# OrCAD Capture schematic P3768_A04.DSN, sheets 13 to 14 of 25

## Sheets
13 0012_BUTTON MCU: size Custom
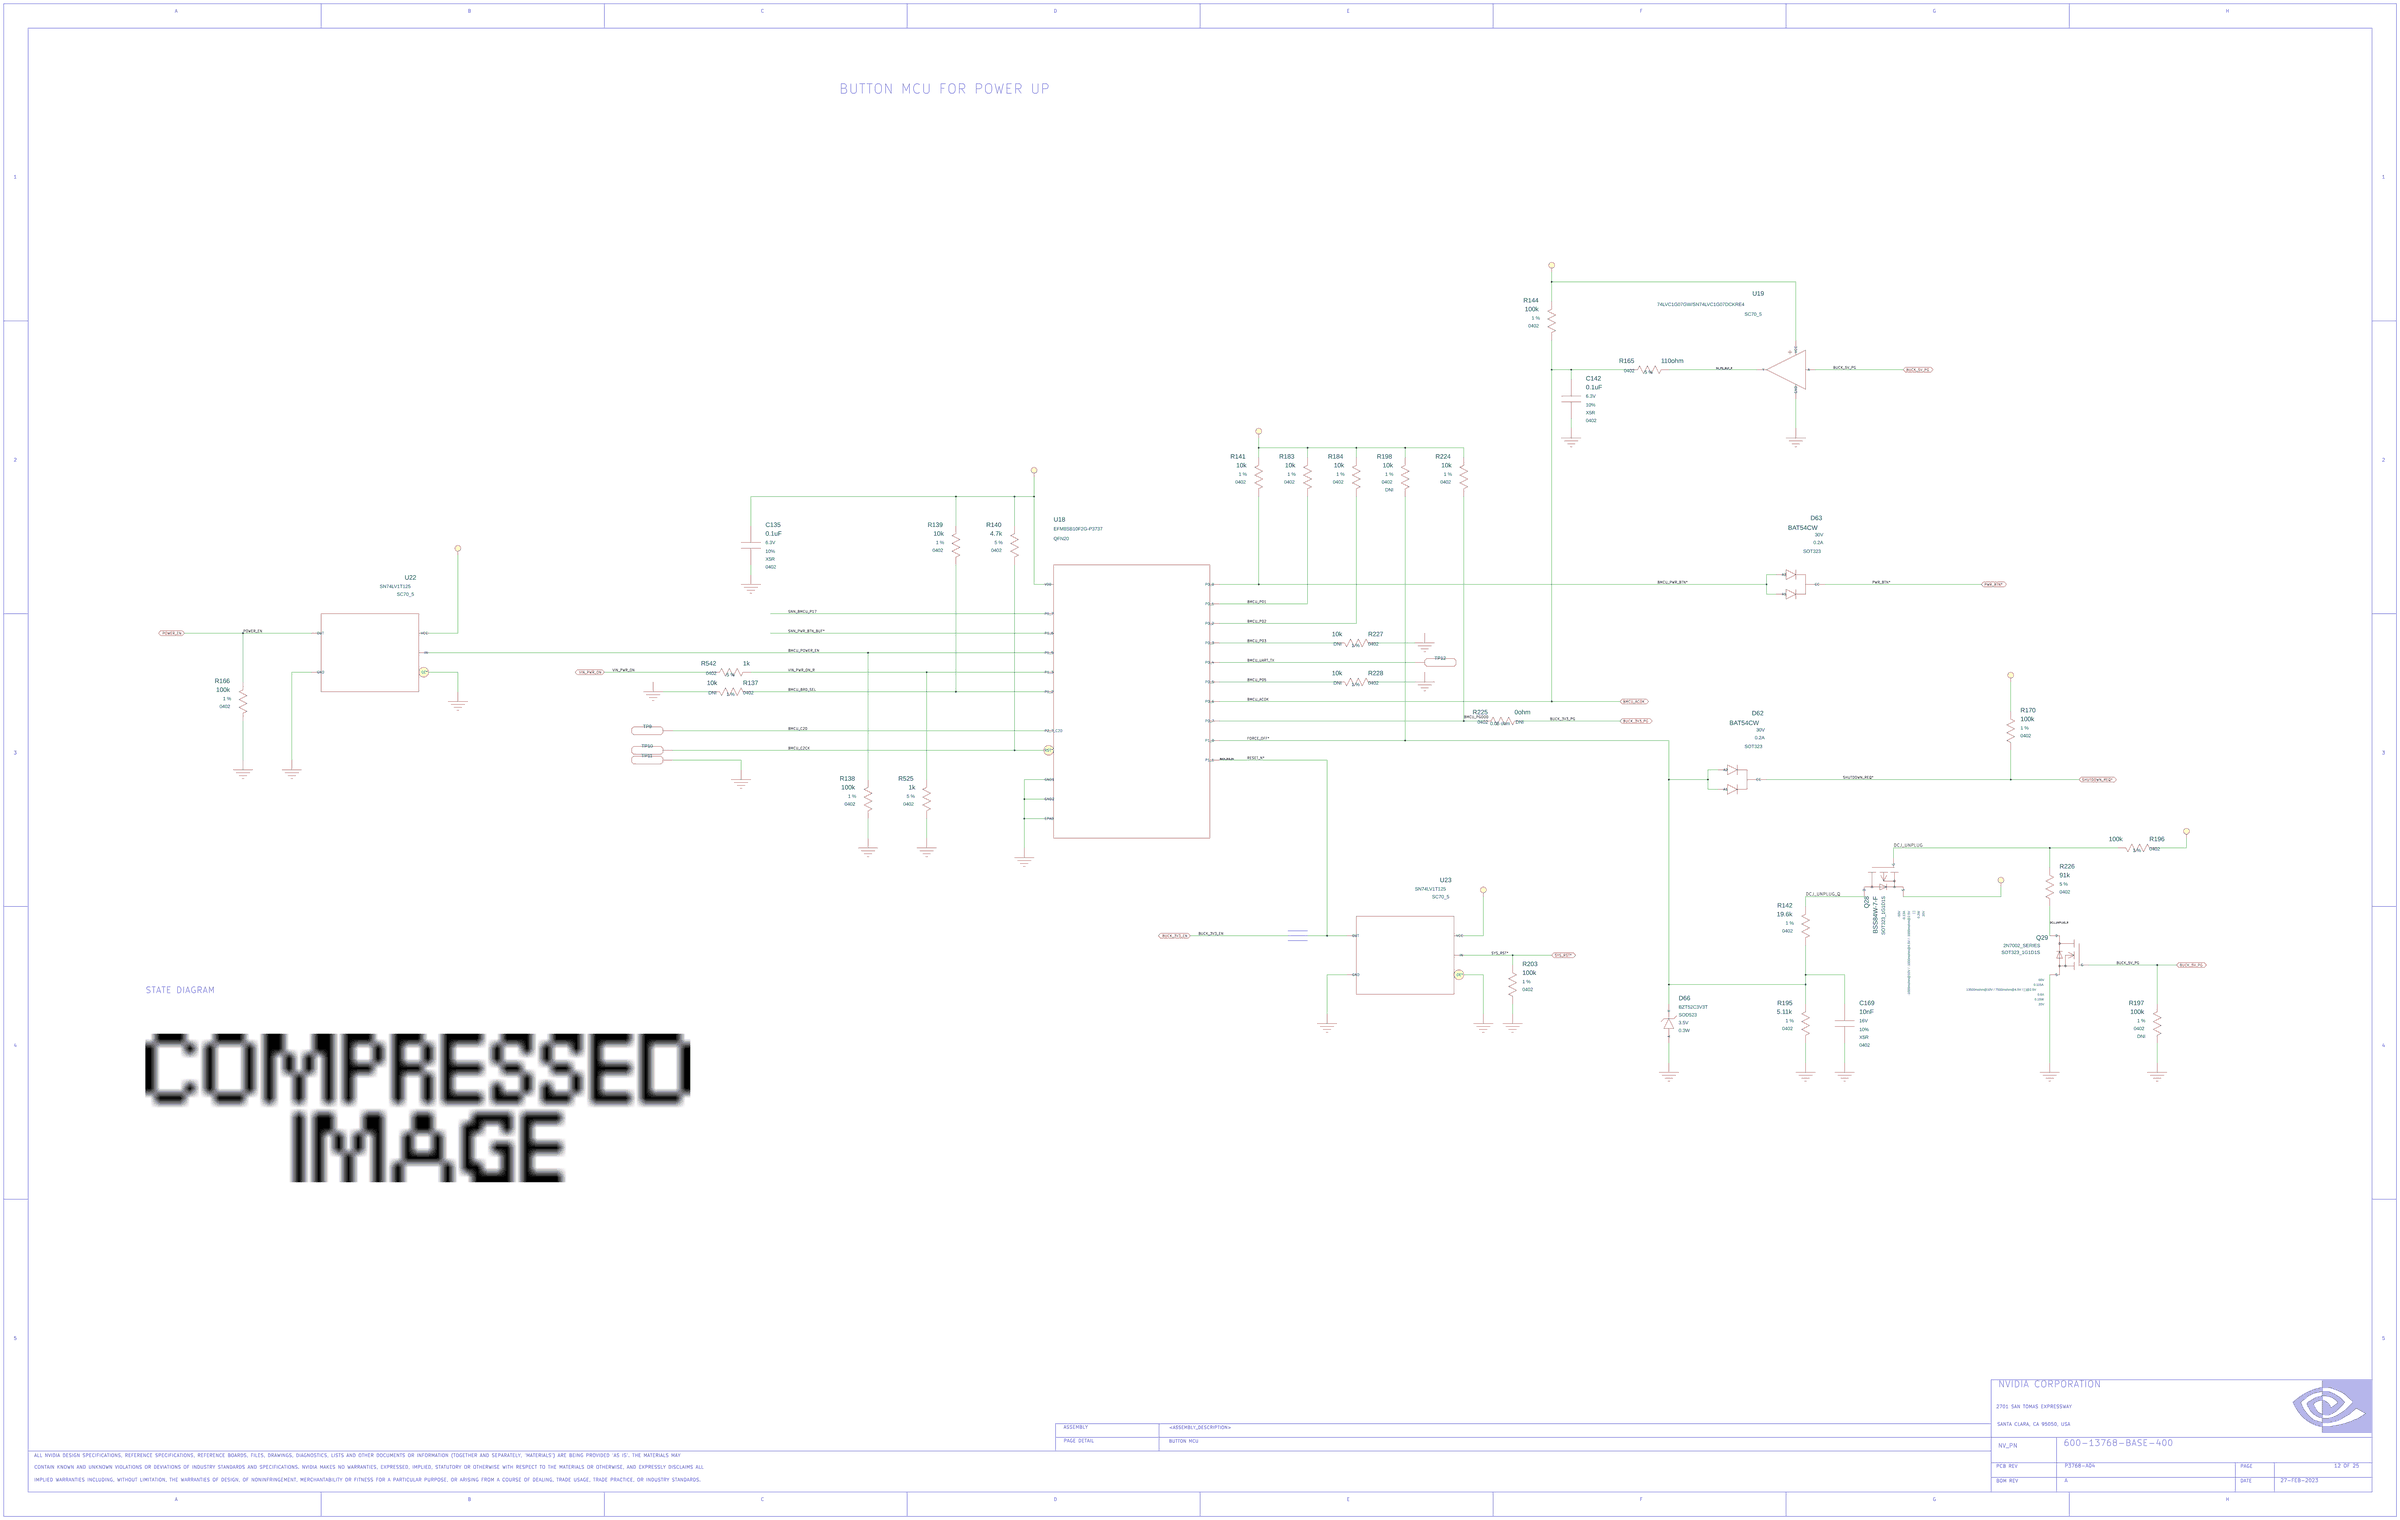
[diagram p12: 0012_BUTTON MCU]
14 0011_1V8 LDO & 3V3 AO Rails: size Custom
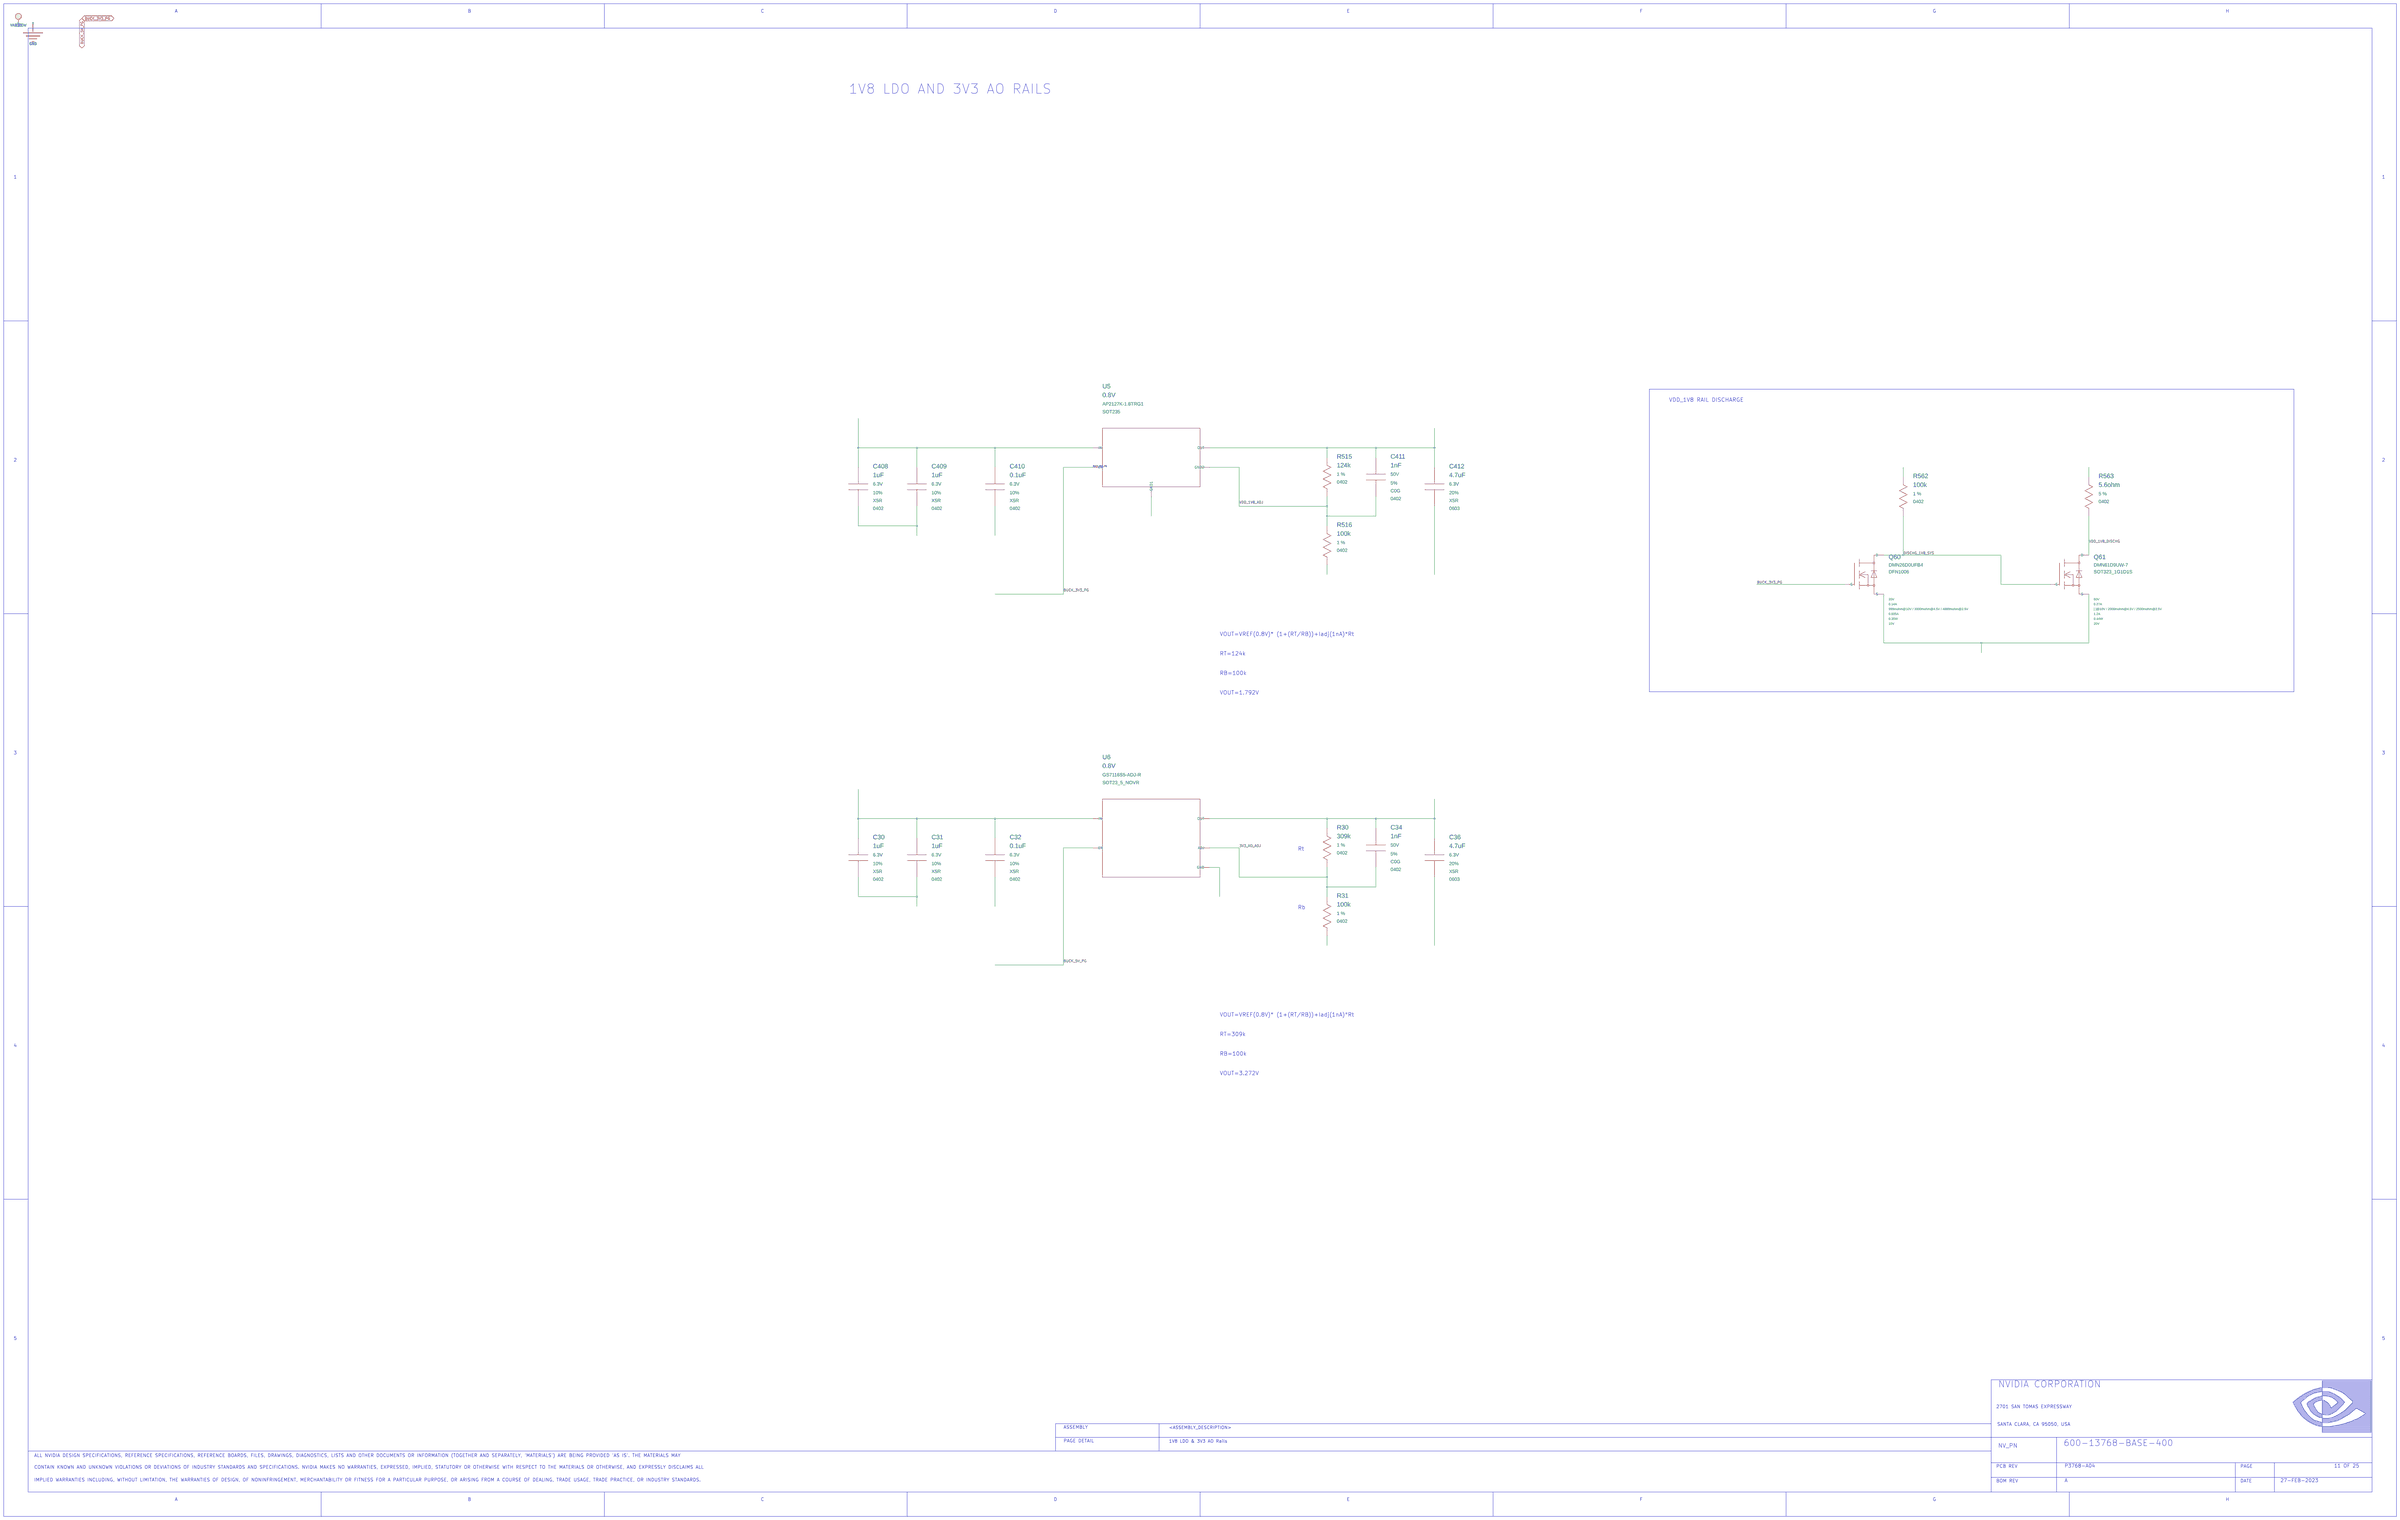
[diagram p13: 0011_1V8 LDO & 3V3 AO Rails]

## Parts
sheet 0011_1V8 LDO & 3V3 AO Rails
C30  1uF  [0402]
C31  1uF  [0402]
C32  0.1uF  [0402]
C34  1nF  [0402]
C36  4.7uF  [0603]
C408  1uF  [0402]
C409  1uF  [0402]
C410  0.1uF  [0402]
C411  1nF  [0402]
C412  4.7uF  [0603]
Q60  Q_FET_N_ENH  [DFET_003_SMD_010X006_B]
Q61  Q_FET_N_ENH  [SOT323]
R30  309k  [0402]
R31  100k  [0402]
R515  124k  [0402]
R516  100k  [0402]
R562  100k  [0402]
R563  5.6ohm  [0402]
U5  0.8V  [SOT23_5]
U6  0.8V  [SOT23_5]
sheet 0012_BUTTON MCU
C135  0.1uF  [0402]
C142  0.1uF  [0402]
C169  10nF  [0402]
D62  D_3PIN_CC  [SOT323]
D63  D_3PIN_CC  [SOT323]
D66  D_ZENER  [DIODE_SMD_SOD523_B]
Q28  Q_FET_P_ENH  [SOT323]
Q29  Q_FET_N_ENH  [SOT323]
R137  10k  [0402]
R138  100k  [0402]
R139  10k  [0402]
R140  4.7k  [0402]
R141  10k  [0402]
R142  19.6k  [0402]
R144  100k  [0402]
R165  110ohm  [0402]
R166  100k  [0402]
R170  100k  [0402]
R183  10k  [0402]
R184  10k  [0402]
R195  5.11k  [0402]
R196  100k  [0402]
R197  100k  [0402]
R198  10k  [0402]
R203  100k  [0402]
R224  10k  [0402]
R225  0ohm  [0402]
R226  91k  [0402]
R227  10k  [0402]
R228  10k  [0402]
R525  1k  [0402]
R542  1k  [0402]
TP9  LABTESTPOINT  [LTPT089C125D]
TP10  LABTESTPOINT  [LTPT089C125D]
TP11  LABTESTPOINT  [LTPT089C125D]
TP12  LABTESTPOINT  [LTPT089C125D]
U18  U_CPU_EFM8SB1  [QFN020Q_P050_0030_T018X018]
U19  U_BUF_OD  [SC70_5]
U22  U_LEVSHFT_3STATE  [SC70_5]
U23  U_LEVSHFT_3STATE  [SC70_5]

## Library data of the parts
C30 = C#1: ASSEMBLY: 3V3_AO; CDS_LIB: discrete; CDS_PART_NAME: C_0402-1UF,X5R,10%,6.3V,039-0008-000; CDS_PHYS_PART_NAME: C_0402-1UF,X5R,10%,6.3V,039-0008-000-039-0008-000,1UF; CDS_SEC: 1; CHIPS_PART_NAME: C; DEVICE_TYPENAME: C_0402-1UFX5R1063V039-0008-000-039-0008-0001UF; DRAWING: @P3768_A04_LIB.P3768_A04(SCH_1):PAGE11; MAT: X5R; MAX_VOLTAGE: 6.3V; NV_PN: 039-0008-000; PATH: I24; PHYS_PAGE: 11; PSPICETEMPLATE: X^@REFDES  %1    %2   @NV_PN; ROT: 0; SEC: 1; SIGNAL_MODEL: nv_cap; TOL: 10%; VER: 1; XY: (-7750,3250)
C31 = C#1: ASSEMBLY: 3V3_AO; CDS_LIB: discrete; CDS_PART_NAME: C_0402-1UF,X5R,10%,6.3V,039-0008-000; CDS_PHYS_PART_NAME: C_0402-1UF,X5R,10%,6.3V,039-0008-000-039-0008-000,1UF; CDS_SEC: 1; CHIPS_PART_NAME: C; DEVICE_TYPENAME: C_0402-1UFX5R1063V039-0008-000-039-0008-0001UF; DRAWING: @P3768_A04_LIB.P3768_A04(SCH_1):PAGE11; MAT: X5R; MAX_VOLTAGE: 6.3V; NV_PN: 039-0008-000; PATH: I23; PHYS_PAGE: 11; PSPICETEMPLATE: X^@REFDES  %1    %2   @NV_PN; ROT: 0; SEC: 1; SIGNAL_MODEL: nv_cap; TOL: 10%; VER: 1; XY: (-7450,3250)
C32 = C#1: ASSEMBLY: 3V3_AO; CDS_LIB: discrete; CDS_PART_NAME: C_0402-0.1UF,X5R,10%,6.3V,039-0007-000; CDS_PHYS_PART_NAME: C_0402-0.1UF,X5R,10%,6.3V,039-0007-000-0.1UF,039-0007-000; CDS_SEC: 1; CHIPS_PART_NAME: C; DEVICE_TYPENAME: C_0402-01UFX5R1063V039-0007-000-01UF039-0007-000; DRAWING: @P3768_A04_LIB.P3768_A04(SCH_1):PAGE11; MAT: X5R; MAX_VOLTAGE: 6.3V; NV_PN: 039-0007-000; PATH: I20; PHYS_PAGE: 11; PSPICETEMPLATE: X^@REFDES  %1    %2   @NV_PN; ROT: 0; SEC: 1; SIGNAL_MODEL: nv_cap; TOL: 10%; VER: 1; XY: (-7050,3250)
C34 = C#1: ASSEMBLY: 3V3_AO; CDS_LIB: discrete; CDS_PART_NAME: C_0402-1NF,C0G,5%,50V,035-0298-000; CDS_PHYS_PART_NAME: C_0402-1NF,C0G,5%,50V,035-0298-000-035-0298-000,1NF; CDS_SEC: 1; CHIPS_PART_NAME: C; DEVICE_TYPENAME: C_0402-1NFC0G550V035-0298-000-035-0298-0001NF; DRAWING: @P3768_A04_LIB.P3768_A04(SCH_1):PAGE11; MAT: C0G; MAX_VOLTAGE: 50V; NV_PN: 035-0298-000; PATH: I14; PHYS_PAGE: 11; PSPICETEMPLATE: X^@REFDES  %1    %2   @NV_PN; ROT: 0; SEC: 1; SIGNAL_MODEL: nv_cap; TOL: 5%; VER: 1; XY: (-5100,3300)
C36 = C#1: ASSEMBLY: 3V3_AO; CDS_LIB: discrete; CDS_PART_NAME: C_0603-4.7UF,X5R,20%,6.3V,032-2124-000; CDS_PHYS_PART_NAME: C_0603-4.7UF,X5R,20%,6.3V,032-2124-000-032-2124-000,4.7UF; CDS_SEC: 1; CHIPS_PART_NAME: C; DEVICE_TYPENAME: C_0603-47UFX5R2063V032-2124-000-032-2124-00047UF; DRAWING: @P3768_A04_LIB.P3768_A04(SCH_1):PAGE11; MAT: X5R; MAX_VOLTAGE: 6.3V; NV_PN: 032-2124-000; PATH: I13; PHYS_PAGE: 11; PSPICETEMPLATE: X^@REFDES  %1    %2   @NV_PN; ROT: 0; SEC: 1; SIGNAL_MODEL: nv_cap; TOL: 20%; VER: 1; XY: (-4800,3250)
C408 = C#1: ASSEMBLY: 1V8_LDO; CDS_LIB: discrete; CDS_PART_NAME: C_0402-1UF,X5R,10%,6.3V,039-0008-000; CDS_PHYS_PART_NAME: C_0402-1UF,X5R,10%,6.3V,039-0008-000-039-0008-000,1UF; CDS_SEC: 1; CHIPS_PART_NAME: C; DEVICE_TYPENAME: C_0402-1UFX5R1063V039-0008-000-039-0008-0001UF; DRAWING: @P3768_A04_LIB.P3768_A04(SCH_1):PAGE11; MAT: X5R; MAX_VOLTAGE: 6.3V; NV_PN: 039-0008-000; PATH: I41; PHYS_PAGE: 11; PSPICETEMPLATE: X^@REFDES  %1    %2   @NV_PN; ROT: 0; SEC: 1; SIGNAL_MODEL: nv_cap; TOL: 10%; VER: 1; XY: (-7750,5150)
C409 = C#1: ASSEMBLY: 1V8_LDO; CDS_LIB: discrete; CDS_PART_NAME: C_0402-1UF,X5R,10%,6.3V,039-0008-000; CDS_PHYS_PART_NAME: C_0402-1UF,X5R,10%,6.3V,039-0008-000-039-0008-000,1UF; CDS_SEC: 1; CHIPS_PART_NAME: C; DEVICE_TYPENAME: C_0402-1UFX5R1063V039-0008-000-039-0008-0001UF; DRAWING: @P3768_A04_LIB.P3768_A04(SCH_1):PAGE11; MAT: X5R; MAX_VOLTAGE: 6.3V; NV_PN: 039-0008-000; PATH: I40; PHYS_PAGE: 11; PSPICETEMPLATE: X^@REFDES  %1    %2   @NV_PN; ROT: 0; SEC: 1; SIGNAL_MODEL: nv_cap; TOL: 10%; VER: 1; XY: (-7450,5150)
C410 = C#1: ASSEMBLY: 1V8_LDO; CDS_LIB: discrete; CDS_PART_NAME: C_0402-0.1UF,X5R,10%,6.3V,039-0007-000; CDS_PHYS_PART_NAME: C_0402-0.1UF,X5R,10%,6.3V,039-0007-000-0.1UF,039-0007-000; CDS_SEC: 1; CHIPS_PART_NAME: C; DEVICE_TYPENAME: C_0402-01UFX5R1063V039-0007-000-01UF039-0007-000; DRAWING: @P3768_A04_LIB.P3768_A04(SCH_1):PAGE11; MAT: X5R; MAX_VOLTAGE: 6.3V; NV_PN: 039-0007-000; PATH: I33; PHYS_PAGE: 11; PSPICETEMPLATE: X^@REFDES  %1    %2   @NV_PN; ROT: 0; SEC: 1; SIGNAL_MODEL: nv_cap; TOL: 10%; VER: 1; XY: (-7050,5150)
C411 = C#1: ASSEMBLY: 1V8_LDO; CDS_LIB: discrete; CDS_PART_NAME: C_0402-1NF,C0G,5%,50V,035-0298-000; CDS_PHYS_PART_NAME: C_0402-1NF,C0G,5%,50V,035-0298-000-035-0298-000,1NF; CDS_SEC: 1; CHIPS_PART_NAME: C; DEVICE_TYPENAME: C_0402-1NFC0G550V035-0298-000-035-0298-0001NF; DRAWING: @P3768_A04_LIB.P3768_A04(SCH_1):PAGE11; MAT: C0G; MAX_VOLTAGE: 50V; NV_PN: 035-0298-000; PATH: I35; PHYS_PAGE: 11; PSPICETEMPLATE: X^@REFDES  %1    %2   @NV_PN; ROT: 0; SEC: 1; SIGNAL_MODEL: nv_cap; TOL: 5%; VER: 1; XY: (-5100,5200)
C412 = C#1: ASSEMBLY: 1V8_LDO; CDS_LIB: discrete; CDS_PART_NAME: C_0603-4.7UF,X5R,20%,6.3V,032-2124-000; CDS_PHYS_PART_NAME: C_0603-4.7UF,X5R,20%,6.3V,032-2124-000-032-2124-000,4.7UF; CDS_SEC: 1; CHIPS_PART_NAME: C; DEVICE_TYPENAME: C_0603-47UFX5R2063V032-2124-000-032-2124-00047UF; DRAWING: @P3768_A04_LIB.P3768_A04(SCH_1):PAGE11; MAT: X5R; MAX_VOLTAGE: 6.3V; NV_PN: 032-2124-000; PATH: I32; PHYS_PAGE: 11; PSPICETEMPLATE: X^@REFDES  %1    %2   @NV_PN; ROT: 0; SEC: 1; SIGNAL_MODEL: nv_cap; TOL: 20%; VER: 1; XY: (-4800,5150)
Q60 = Q_FET_N_ENH#1: ASSEMBLY: 1V8_LDO; CDS_LIB: discrete; CDS_PART_NAME: Q_FET_N_ENH_DFN1006-DMN26D0UFB4,20V,999MOHM@10V / 3000MOHM@4.5V / 4000MOHM@2.5V,0.14A,0.805A,10V,0.35W,999NC@10V / 0NC@4.5V / 999NC@2.5V,300-0868-000; CDS_PHYS_PART_NAME: Q_FET_N_ENH_DFN1006-DMN26D0UFB4,20V,999MOHM@10V / 3000MOHM@4.5V / 4000MOHM@2.5V,0.14A,0.805A,10V,0.35W,999NC@10V / 0NC@4.5V / B; CDS_SEC: 1; CONTINUOUS_CURRENT: 0.14A; CaptureCellPackProp: Q_FET_N_ENH##1; DEVICE_TYPENAME: Q_FET_N_ENH_DFN1006-DMN26D0UFB420V999MOHM10V3000MOHM45V4000MOHM25V014A0805A10V035W999NC10V0NC45VB; DRAWING: @P3768_A04_LIB.P3768_A04(SCH_1):PAGE11; MAX_CURRENT: 0.805A; MAX_VOLTAGE: 20V; MAX_WATTAGE: 0.35W; NV_NAME: DMN26D0UFB4; NV_PN: 300-0868-000; PACK_TYPE: DFN1006; PATH: I56; PHYS_PAGE: 11; Q_G: 999nC@10V / 0nC@4.5V / 999nC@2.5V; ROT: 0; R_DS_ON: 999mohm@10V / 3000mohm@4.5V / 4000mohm@2.5V; SEC: 1; VER: 2; V_BE_GS: 10V; XY: (-2600,4700)
Q61 = Q_FET_N_ENH#1: ASSEMBLY: 1V8_LDO; CDS_LIB: discrete; CDS_PART_NAME: Q_FET_N_ENH_SOT323_1G1D1S-DMN61D9UW-7,60V,[ ]@10V / 2000MOHM@4.5V / 2500MOHM@2.5V,0.27A,1.2A,20V,0.44W,[ ]@10V / 0.4NC@4.5V / [ ]@2.5V,300-1185-000; CDS_PHYS_PART_NAME: Q_FET_N_ENH_SOT323_1G1D1S-DMN61D9UW-7,60V,[ ]@10V / 2000MOHM@4.5V / 2500MOHM@2.5V,0.27A,1.2A,20V,0.44W,[ ]@10V / 0.4NC@4.5V / B; CDS_SEC: 1; CONTINUOUS_CURRENT: 0.27A; CaptureCellPackProp: Q_FET_N_ENH##1; DEVICE_TYPENAME: Q_FET_N_ENH_SOT323_1G1D1S-DMN61D9UW-760V10V2000MOHM45V2500MOHM25V027A12A20V044W10V04NC45VB; DRAWING: @P3768_A04_LIB.P3768_A04(SCH_1):PAGE11; MAX_CURRENT: 1.2A; MAX_VOLTAGE: 60V; MAX_WATTAGE: 0.44W; NV_NAME: DMN61D9UW-7; NV_PN: 300-1185-000; PACK_TYPE: SOT323_1G1D1S; PATH: I53; PHYS_PAGE: 11; Q_G: [ ]@10V / 0.4nC@4.5V / [ ]@2.5V; ROT: 0; R_DS_ON: [ ]@10V / 2000mohm@4.5V / 2500mohm@2.5V; SEC: 1; VER: 2; V_BE_GS: 20V; XY: (-1550,4700)
R30 = R: ASSEMBLY: 3V3_AO; CDS_LIB: discrete; CDS_PART_NAME: R_0402-309K,1 %,62.5MW,195-0241-000; CDS_PHYS_PART_NAME: R_0402-309K,1 %,62.5MW,195-0241-000-195-0241-000,309K; CDS_SEC: 1; DEVICE_TYPENAME: R_0402-309K1625MW195-0241-000-195-0241-000309K; DRAWING: @P3768_A04_LIB.P3768_A04(SCH_1):PAGE11; MAX_WATTAGE: 62.5mW; NV_PN: 195-0241-000; PATH: I16; PHYS_PAGE: 11; PSPICETEMPLATE: X^@REFDES  %1    %2   @NV_PN; ROT: 0; SEC: 1; SIGNAL_MODEL: nv_res; TOL: 1 %; VER: 2; XY: (-5350,3300)
R31 = R: ASSEMBLY: 3V3_AO; CDS_LIB: discrete; CDS_PART_NAME: R_0402-100K,1 %,62.5MW,195-0005-000; CDS_PHYS_PART_NAME: R_0402-100K,1 %,62.5MW,195-0005-000-100K,195-0005-000; CDS_SEC: 1; DEVICE_TYPENAME: R_0402-100K1625MW195-0005-000-100K195-0005-000; DRAWING: @P3768_A04_LIB.P3768_A04(SCH_1):PAGE11; MAX_WATTAGE: 62.5mW; NV_PN: 195-0005-000; PATH: I18; PHYS_PAGE: 11; PSPICETEMPLATE: X^@REFDES  %1    %2   @NV_PN; ROT: 0; SEC: 1; SIGNAL_MODEL: nv_res; TOL: 1 %; VER: 2; XY: (-5350,2950)
R515 = R: ASSEMBLY: 1V8_LDO; CDS_LIB: discrete; CDS_PART_NAME: R_0402-124K,1 %,62.5MW,195-0051-000; CDS_PHYS_PART_NAME: R_0402-124K,1 %,62.5MW,195-0051-000-124K,195-0051-000; CDS_SEC: 1; DEVICE_TYPENAME: R_0402-124K1625MW195-0051-000-124K195-0051-000; DRAWING: @P3768_A04_LIB.P3768_A04(SCH_1):PAGE11; MAX_WATTAGE: 62.5mW; NV_PN: 195-0051-000; PATH: I29; PHYS_PAGE: 11; ROT: 0; SEC: 1; SIGNAL_MODEL: nv_res; TOL: 1 %; VER: 2; XY: (-5350,5200)
R516 = R: ASSEMBLY: 1V8_LDO; CDS_LIB: discrete; CDS_PART_NAME: R_0402-100K,1 %,62.5MW,195-0005-000; CDS_PHYS_PART_NAME: R_0402-100K,1 %,62.5MW,195-0005-000-100K,195-0005-000; CDS_SEC: 1; DEVICE_TYPENAME: R_0402-100K1625MW195-0005-000-100K195-0005-000; DRAWING: @P3768_A04_LIB.P3768_A04(SCH_1):PAGE11; MAX_WATTAGE: 62.5mW; NV_PN: 195-0005-000; PATH: I30; PHYS_PAGE: 11; ROT: 0; SEC: 1; SIGNAL_MODEL: nv_res; TOL: 1 %; VER: 2; XY: (-5350,4850)
R562 = R: ASSEMBLY: 1V8_LDO; CDS_LIB: discrete; CDS_PART_NAME: R_0402-100K,1 %,62.5MW,195-0005-000; CDS_PHYS_PART_NAME: R_0402-100K,1 %,62.5MW,195-0005-000-100K,195-0005-000; CDS_SEC: 1; DEVICE_TYPENAME: R_0402-100K1625MW195-0005-000-100K195-0005-000; DRAWING: @P3768_A04_LIB.P3768_A04(SCH_1):PAGE11; MAX_WATTAGE: 62.5mW; NV_PN: 195-0005-000; PATH: I57; PHYS_PAGE: 11; ROT: 0; SEC: 1; SIGNAL_MODEL: nv_res; TOL: 1 %; VER: 2; XY: (-2400,5100)
R563 = R: ASSEMBLY: 1V8_LDO; CDS_LIB: discrete; CDS_PART_NAME: R_0402-5.6OHM,5 %,62.5MW,195-0609-000; CDS_PHYS_PART_NAME: R_0402-5.6OHM,5 %,62.5MW,195-0609-000-195-0609-000,5.6OHM; CDS_SEC: 1; DEVICE_TYPENAME: R_0402-56OHM5625MW195-0609-000-195-0609-00056OHM; DRAWING: @P3768_A04_LIB.P3768_A04(SCH_1):PAGE11; MAX_WATTAGE: 62.5mW; NV_PN: 195-0609-000; PATH: I55; PHYS_PAGE: 11; ROT: 0; SEC: 1; TOL: 5 %; VER: 2; XY: (-1450,5100)
U5 = U_VREG_5PIN#1: ASSEMBLY: 1V8_LDO; CDS_LIB: power_supply; CDS_PART_NAME: U_VREG_5PIN_SOT235-AP2127K-1.8TRG1,LOW DROP OUT/FIXED,0.7V@0.3A,1.8V..1.8V,2%,0.8V,6V,0.3A,999W,315-1473-000; CDS_PHYS_PART_NAME: U_VREG_5PIN_SOT235-AP2127K-1.8TRG1,LOW DROP OUT/FIXED,0.7V@0.3A,1.8V..1.8V,2%,0.8V,6V,0.3A,999W,315-1473-000-0.8V,315-1473-000; CDS_SEC: 1; CHIPS_PART_NAME: U_VREG_5PIN; DEVICE_TYPENAME: U_VREG_5PIN_SOT235-AP2127K-18TRG1LOWDROPOUTFIXED07V03A18V18V208V6V03A999W315-1473-000-08V315-1473-000; DRAWING: @P3768_A04_LIB.P3768_A04(SCH_1):PAGE11; FORWARD_VOLTAGE: 0.7V@0.3A; MAX_CURRENT: 0.3A; MAX_VOLTAGE: 6V; MAX_WATTAGE: 999W; NV_NAME: AP2127K-1.8TRG1; NV_PN: 315-1473-000; OUTPUT_VOLTAGE: 1.8V..1.8V; PACK_TYPE: SOT235; PATH: I58; PHYS_PAGE: 11; ROT: 0; SEC: 1; TOL: 2%; TYPE: Low Drop Out/Fixed; VER: 15; XY: (-6250,5300)
U6 = U_LDO: ASSEMBLY: 3V3_AO; CDS_LIB: power_supply; CDS_PART_NAME: U_LDO_SOT23_5_NOVR-GS7116S5-ADJ-R,STANDARD,0.45V@0.5A,0.8V..5V,2%,0.8V,6.5V,0.5A,0.4W,315-1022-000; CDS_PHYS_PART_NAME: U_LDO_SOT23_5_NOVR-GS7116S5-ADJ-R,STANDARD,0.45V@0.5A,0.8V..5V,2%,0.8V,6.5V,0.5A,0.4W,315-1022-000-0.8V,315-1022-000; CDS_SEC: 1; DEVICE_TYPENAME: U_LDO_SOT23_5_NOVR-GS7116S5-ADJ-RSTANDARD045V05A08V5V208V65V05A04W315-1022-000-08V315-1022-000; DRAWING: @P3768_A04_LIB.P3768_A04(SCH_1):PAGE11; FORWARD_VOLTAGE: 0.45V@0.5A; MAX_CURRENT: 0.5A; MAX_VOLTAGE: 6.5V; MAX_WATTAGE: 0.4W; NV_NAME: GS7116S5-ADJ-R; NV_PN: 315-1022-000; OUTPUT_VOLTAGE: 0.8V..5V; PACK_TYPE: SOT23_5_NOVR; PATH: I10; PHYS_PAGE: 11; ROT: 0; SEC: 1; TOL: 2%; TYPE: Standard; VER: 3; XY: (-6250,3350)
C135 = C#1: ASSEMBLY: BUTTON_MCU; CDS_LIB: discrete; CDS_PART_NAME: C_0402-0.1UF,X5R,10%,6.3V,039-0007-000; CDS_PHYS_PART_NAME: C_0402-0.1UF,X5R,10%,6.3V,039-0007-000-0.1UF,039-0007-000; CDS_SEC: 1; CHIPS_PART_NAME: C; DEVICE_TYPENAME: C_0402-01UFX5R1063V039-0007-000-01UF039-0007-000; DRAWING: @P3768_A04_LIB.P3768_A04(SCH_1):PAGE12; MAT: X5R; MAX_VOLTAGE: 6.3V; NV_PN: 039-0007-000; PATH: I27; PHYS_PAGE: 12; PSPICETEMPLATE: X^@REFDES  %1    %2   @NV_PN; ROT: 0; SEC: 1; SIGNAL_MODEL: nv_cap; TOL: 10%; VER: 1; XY: (-8300,4850)
C142 = C#1: ASSEMBLY: BUTTON_MCU; CDS_LIB: discrete; CDS_PART_NAME: C_0402-0.1UF,X5R,10%,6.3V,039-0007-000; CDS_PHYS_PART_NAME: C_0402-0.1UF,X5R,10%,6.3V,039-0007-000-0.1UF,039-0007-000; CDS_SEC: 1; CHIPS_PART_NAME: C; DEVICE_TYPENAME: C_0402-01UFX5R1063V039-0007-000-01UF039-0007-000; DRAWING: @P3768_A04_LIB.P3768_A04(SCH_1):PAGE12; MAT: X5R; MAX_VOLTAGE: 6.3V; NV_PN: 039-0007-000; PATH: I49; PHYS_PAGE: 12; PSPICETEMPLATE: X^@REFDES  %1    %2   @NV_PN; ROT: 0; SEC: 1; SIGNAL_MODEL: nv_cap; TOL: 10%; VER: 1; XY: (-4100,5600)
C169 = C#1: ASSEMBLY: BUTTON_MCU; CDS_LIB: discrete; CDS_PART_NAME: C_0402-10NF,X5R,10%,16V,039-0024-000; CDS_PHYS_PART_NAME: C_0402-10NF,X5R,10%,16V,039-0024-000-039-0024-000,10NF; CDS_SEC: 1; CHIPS_PART_NAME: C; DEVICE_TYPENAME: C_0402-10NFX5R1016V039-0024-000-039-0024-00010NF; DRAWING: @P3768_A04_LIB.P3768_A04(SCH_1):PAGE12; MAT: X5R; MAX_VOLTAGE: 16V; NV_PN: 039-0024-000; PATH: I82; PHYS_PAGE: 12; PSPICETEMPLATE: X^@REFDES  %1    %2   @NV_PN; ROT: 0; SEC: 1; SIGNAL_MODEL: nv_cap; TOL: 10%; VER: 1; XY: (-2700,2400)
D62 = D_3PIN_CC: ASSEMBLY: BUTTON_MCU; CDS_LIB: discrete; CDS_PART_NAME: D_3PIN_CC_SOT323-BAT54CW,1 PAIR - COMMON CATHODE,30V,0.6A,1V@0.1A,0.2A,091-0022-000; CDS_PHYS_PART_NAME: D_3PIN_CC_SOT323-BAT54CW,1 PAIR - COMMON CATHODE,30V,0.6A,1V@0.1A,0.2A,091-0022-000-091-0022-000; CDS_SEC: 1; CONFIGURATION: 1 Pair - Common Cathode; CONTINUOUS_CURRENT: 0.2A; DEVICE_TYPENAME: D_3PIN_CC_SOT323-BAT54CW1PAIR-COMMONCATHODE30V06A1V01A02A091-0022-000-091-0022-000; DRAWING: @P3768_A04_LIB.P3768_A04(SCH_1):PAGE12; FORWARD_VOLTAGE: 1V@0.1A; MAX_CURRENT: 0.6A; MAX_VOLTAGE: 30V; NV_NAME: BAT54CW; NV_PN: 091-0022-000; PATH: I57; PHYS_PAGE: 12; ROT: 2; SEC: 1; VER: 1; XY: (-3200,3650)
D63 = D_3PIN_CC: ASSEMBLY: BUTTON_MCU; CDS_LIB: discrete; CDS_PART_NAME: D_3PIN_CC_SOT323-BAT54CW,1 PAIR - COMMON CATHODE,30V,0.6A,1V@0.1A,0.2A,091-0022-000; CDS_PHYS_PART_NAME: D_3PIN_CC_SOT323-BAT54CW,1 PAIR - COMMON CATHODE,30V,0.6A,1V@0.1A,0.2A,091-0022-000-091-0022-000; CDS_SEC: 1; CONFIGURATION: 1 Pair - Common Cathode; CONTINUOUS_CURRENT: 0.2A; DEVICE_TYPENAME: D_3PIN_CC_SOT323-BAT54CW1PAIR-COMMONCATHODE30V06A1V01A02A091-0022-000-091-0022-000; DRAWING: @P3768_A04_LIB.P3768_A04(SCH_1):PAGE12; FORWARD_VOLTAGE: 1V@0.1A; MAX_CURRENT: 0.6A; MAX_VOLTAGE: 30V; NV_NAME: BAT54CW; NV_PN: 091-0022-000; PATH: I58; PHYS_PAGE: 12; ROT: 2; SEC: 1; VER: 1; XY: (-2900,4650)
D66 = D_ZENER: ASSEMBLY: BUTTON_MCU; CDS_LIB: discrete; CDS_PART_NAME: D_ZENER_SOD523-BZT52C3V3T,3.5V,5MA,0.9V@10MA,0.3W,090-0343-000; CDS_PHYS_PART_NAME: D_ZENER_SOD523-BZT52C3V3T,3.5V,5MA,0.9V@10MA,0.3W,090-0343-000-090-0343-000; CDS_SEC: 1; CONTINUOUS_CURRENT: 0.3W; DEVICE_TYPENAME: D_ZENER_SOD523-BZT52C3V3T35V5MA09V10MA03W090-0343-000-090-0343-000; DRAWING: @P3768_A04_LIB.P3768_A04(SCH_1):PAGE12; FORWARD_VOLTAGE: 0.9V@10mA; MAX_CURRENT: 5mA; MAX_VOLTAGE: 3.5V; NV_NAME: BZT52C3V3T; NV_PN: 090-0343-000; PACK_TYPE: SOD523; PATH: I91; PHYS_PAGE: 12; ROT: 0; SEC: 1; VER: 2; XY: (-3600,2400)
Q28 = Q_FET_P_ENH#1: ASSEMBLY: BUTTON_MCU; CDS_LIB: discrete; CDS_PART_NAME: Q_FET_P_ENH_SOT323_1G1D1S-BSS84W-7-F,-50V,-1000MOHM@10V / -1000MOHM@4.5V / -1000MOHM@2.5V,-0.13A,[ ],20V,0.2W,[ ]@10V / [ ]@4.5V / [ ]@2.5V,300-0518-000; CDS_PHYS_PART_NAME: Q_FET_P_ENH_SOT323_1G1D1S-BSS84W-7-F,-50V,-1000MOHM@10V / -1000MOHM@4.5V / -1000MOHM@2.5V,-0.13A,[ ],20V,0.2W,[ ]@10V / [ ]@4.B; CDS_SEC: 1; CONTINUOUS_CURRENT: -0.13A; DEVICE_TYPENAME: Q_FET_P_ENH_SOT323_1G1D1S-BSS84W-7-F-50V-1000MOHM10V-1000MOHM45V-1000MOHM25V-013A20V02W10V4B; DRAWING: @P3768_A04_LIB.P3768_A04(SCH_1):PAGE12; MAX_CURRENT: [ ]; MAX_VOLTAGE: -50V; MAX_WATTAGE: 0.2W; NV_NAME: BSS84W-7-F; NV_PN: 300-0518-000; PACK_TYPE: SOT323_1G1D1S; PATH: I78; PHYS_PAGE: 12; Q_G: [ ]@10V / [ ]@4.5V / [ ]@2.5V; ROT: 3; R_DS_ON: -1000mohm@10V / -1000mohm@4.5V / -1000mohm@2.5V; SEC: 1; VER: 2; V_BE_GS: 20V; XY: (-2500,3150)
Q29 = Q_FET_N_ENH#1: ASSEMBLY: BUTTON_MCU; CDS_LIB: discrete; CDS_PART_NAME: Q_FET_N_ENH_SOT323_1G1D1S-2N7002_SERIES,60V,13500MOHM@10V / 7500MOHM@4.5V / [ ]@2.5V,0.115A,0.8A,20V,0.15W,[ ]@10V / 0.5NC@4.5V / [ ]@2.5V,300-1133-000; CDS_PHYS_PART_NAME: Q_FET_N_ENH_SOT323_1G1D1S-2N7002_SERIES,60V,13500MOHM@10V / 7500MOHM@4.5V / [ ]@2.5V,0.115A,0.8A,20V,0.15W,[ ]@10V / 0.5NC@4.5B; CDS_SEC: 1; CONTINUOUS_CURRENT: 0.115A; CaptureCellPackProp: Q_FET_N_ENH##1; DEVICE_TYPENAME: Q_FET_N_ENH_SOT323_1G1D1S-2N7002_SERIES60V13500MOHM10V7500MOHM45V25V0115A08A20V015W10V05NC45B; DRAWING: @P3768_A04_LIB.P3768_A04(SCH_1):PAGE12; MAX_CURRENT: 0.8A; MAX_VOLTAGE: 60V; MAX_WATTAGE: 0.15W; NV_NAME: 2N7002_SERIES; NV_PN: 300-1133-000; PACK_TYPE: SOT323_1G1D1S; PATH: I89; PHYS_PAGE: 12; Q_G: [ ]@10V / 0.5nC@4.5V / [ ]@2.5V; ROT: 2; R_DS_ON: 13500mohm@10V / 7500mohm@4.5V / [ ]@2.5V; SEC: 1; VER: 2; V_BE_GS: 20V; XY: (-1550,2750)
R137 = R#1: ASSEMBLY: BUTTON_MCU; CDS_LIB: discrete; CDS_PART_NAME: R_0402-10K,1 %,62.5MW,195-0004-000; CDS_PHYS_PART_NAME: R_0402-10K,1 %,62.5MW,195-0004-000-10K,195-0004-000; CDS_SEC: 1; CHIPS_PART_NAME: R; DEVICE_TYPENAME: R_0402-10K1625MW195-0004-000-10K195-0004-000; DRAWING: @P3768_A04_LIB.P3768_A04(SCH_1):PAGE12; MAX_WATTAGE: 62.5mW; NV_PN: 195-0004-000; PATH: I36; PHYS_PAGE: 12; PSPICETEMPLATE: X^@REFDES  %1    %2   @NV_PN; ROT: 2; SEC: 1; SIGNAL_MODEL: nv_res; SKU: DNI; TOL: 1 %; VER: 1; XY: (-8400,4100)
R138 = R: ASSEMBLY: BUTTON_MCU; CDS_LIB: discrete; CDS_PART_NAME: R_0402-100K,1 %,62.5MW,195-0005-000; CDS_PHYS_PART_NAME: R_0402-100K,1 %,62.5MW,195-0005-000-100K,195-0005-000; CDS_SEC: 1; DEVICE_TYPENAME: R_0402-100K1625MW195-0005-000-100K195-0005-000; DRAWING: @P3768_A04_LIB.P3768_A04(SCH_1):PAGE12; MAX_WATTAGE: 62.5mW; NV_PN: 195-0005-000; PATH: I31; PHYS_PAGE: 12; PSPICETEMPLATE: X^@REFDES  %1    %2   @NV_PN; ROT: 2; SEC: 1; SIGNAL_MODEL: nv_res; TOL: 1 %; VER: 2; XY: (-7700,3550)
R139 = R: ASSEMBLY: BUTTON_MCU; CDS_LIB: discrete; CDS_PART_NAME: R_0402-10K,1 %,62.5MW,195-0004-000; CDS_PHYS_PART_NAME: R_0402-10K,1 %,62.5MW,195-0004-000-10K,195-0004-000; CDS_SEC: 1; DEVICE_TYPENAME: R_0402-10K1625MW195-0004-000-10K195-0004-000; DRAWING: @P3768_A04_LIB.P3768_A04(SCH_1):PAGE12; MAX_WATTAGE: 62.5mW; NV_PN: 195-0004-000; PATH: I24; PHYS_PAGE: 12; PSPICETEMPLATE: X^@REFDES  %1    %2   @NV_PN; ROT: 2; SEC: 1; SIGNAL_MODEL: nv_res; TOL: 1 %; VER: 2; XY: (-7250,4850)
R140 = R: ASSEMBLY: BUTTON_MCU; CDS_LIB: discrete; CDS_PART_NAME: R_0402-4.7K,5 %,62.5MW,195-0598-000; CDS_PHYS_PART_NAME: R_0402-4.7K,5 %,62.5MW,195-0598-000-195-0598-000,4.7K; CDS_SEC: 1; DEVICE_TYPENAME: R_0402-47K5625MW195-0598-000-195-0598-00047K; DRAWING: @P3768_A04_LIB.P3768_A04(SCH_1):PAGE12; MAX_WATTAGE: 62.5mW; NV_PN: 195-0598-000; PATH: I21; PHYS_PAGE: 12; PSPICETEMPLATE: X^@REFDES  %1    %2   @NV_PN; ROT: 2; SEC: 1; SIGNAL_MODEL: nv_res; TOL: 5 %; VER: 2; XY: (-6950,4850)
R141 = R: ASSEMBLY: BUTTON_MCU; CDS_LIB: discrete; CDS_PART_NAME: R_0402-10K,1 %,62.5MW,195-0004-000; CDS_PHYS_PART_NAME: R_0402-10K,1 %,62.5MW,195-0004-000-10K,195-0004-000; CDS_SEC: 1; DEVICE_TYPENAME: R_0402-10K1625MW195-0004-000-10K195-0004-000; DRAWING: @P3768_A04_LIB.P3768_A04(SCH_1):PAGE12; MAX_WATTAGE: 62.5mW; NV_PN: 195-0004-000; PATH: I18; PHYS_PAGE: 12; PSPICETEMPLATE: X^@REFDES  %1    %2   @NV_PN; ROT: 2; SEC: 1; SIGNAL_MODEL: nv_res; TOL: 1 %; VER: 2; XY: (-5700,5200)
R142 = R: ASSEMBLY: BUTTON_MCU; CDS_LIB: discrete; CDS_PART_NAME: R_0402-19.6K,1 %,62.5MW,195-0145-000; CDS_PHYS_PART_NAME: R_0402-19.6K,1 %,62.5MW,195-0145-000-19.6K,195-0145-000; CDS_SEC: 1; DEVICE_TYPENAME: R_0402-196K1625MW195-0145-000-196K195-0145-000; DRAWING: @P3768_A04_LIB.P3768_A04(SCH_1):PAGE12; MAX_WATTAGE: 62.5mW; NV_PN: 195-0145-000; PATH: I6; PHYS_PAGE: 12; PSPICETEMPLATE: X^@REFDES  %1    %2   @NV_PN; ROT: 2; SEC: 1; SIGNAL_MODEL: nv_res; TOL: 1 %; VER: 2; XY: (-2900,2900)
R144 = R: ASSEMBLY: BUTTON_MCU; CDS_LIB: discrete; CDS_PART_NAME: R_0402-100K,1 %,62.5MW,195-0005-000; CDS_PHYS_PART_NAME: R_0402-100K,1 %,62.5MW,195-0005-000-100K,195-0005-000; CDS_SEC: 1; DEVICE_TYPENAME: R_0402-100K1625MW195-0005-000-100K195-0005-000; DRAWING: @P3768_A04_LIB.P3768_A04(SCH_1):PAGE12; MAX_WATTAGE: 62.5mW; NV_PN: 195-0005-000; PATH: I5; PHYS_PAGE: 12; PSPICETEMPLATE: X^@REFDES  %1    %2   @NV_PN; ROT: 2; SEC: 1; SIGNAL_MODEL: nv_res; TOL: 1 %; VER: 2; XY: (-4200,6000)
R165 = R#1: ASSEMBLY: BUTTON_MCU; CDS_LIB: discrete; CDS_PART_NAME: R_0402-110OHM,5 %,62.5MW,195-0492-000; CDS_PHYS_PART_NAME: R_0402-110OHM,5 %,62.5MW,195-0492-000-110OHM,195-0492-000; CDS_SEC: 1; CHIPS_PART_NAME: R; DEVICE_TYPENAME: R_0402-110OHM5625MW195-0492-000-110OHM195-0492-000; DRAWING: @P3768_A04_LIB.P3768_A04(SCH_1):PAGE12; MAX_WATTAGE: 62.5mW; NV_PN: 195-0492-000; PATH: I56; PHYS_PAGE: 12; PSPICETEMPLATE: X^@REFDES  %1    %2   @NV_PN; ROT: 0; SEC: 1; SIGNAL_MODEL: nv_res; TOL: 5 %; VER: 1; XY: (-3700,5750)
R166 = R: ASSEMBLY: BUTTON_MCU; CDS_LIB: discrete; CDS_PART_NAME: R_0402-100K,1 %,62.5MW,195-0005-000; CDS_PHYS_PART_NAME: R_0402-100K,1 %,62.5MW,195-0005-000-100K,195-0005-000; CDS_SEC: 1; DEVICE_TYPENAME: R_0402-100K1625MW195-0005-000-100K195-0005-000; DRAWING: @P3768_A04_LIB.P3768_A04(SCH_1):PAGE12; MAX_WATTAGE: 62.5mW; NV_PN: 195-0005-000; PATH: I66; PHYS_PAGE: 12; PSPICETEMPLATE: X^@REFDES  %1    %2   @NV_PN; ROT: 2; SEC: 1; SIGNAL_MODEL: nv_res; TOL: 1 %; VER: 2; XY: (-10900,4050)
R170 = R: ASSEMBLY: BUTTON_MCU; CDS_LIB: discrete; CDS_PART_NAME: R_0402-100K,1 %,62.5MW,195-0005-000; CDS_PHYS_PART_NAME: R_0402-100K,1 %,62.5MW,195-0005-000-100K,195-0005-000; CDS_SEC: 1; DEVICE_TYPENAME: R_0402-100K1625MW195-0005-000-100K195-0005-000; DRAWING: @P3768_A04_LIB.P3768_A04(SCH_1):PAGE12; MAX_WATTAGE: 62.5mW; NV_PN: 195-0005-000; PATH: I61; PHYS_PAGE: 12; PSPICETEMPLATE: X^@REFDES  %1    %2   @NV_PN; ROT: 0; SEC: 1; SIGNAL_MODEL: nv_res; TOL: 1 %; VER: 2; XY: (-1850,3900)
R183 = R: ASSEMBLY: BUTTON_MCU; CDS_LIB: discrete; CDS_PART_NAME: R_0402-10K,1 %,62.5MW,195-0004-000; CDS_PHYS_PART_NAME: R_0402-10K,1 %,62.5MW,195-0004-000-10K,195-0004-000; CDS_SEC: 1; DEVICE_TYPENAME: R_0402-10K1625MW195-0004-000-10K195-0004-000; DRAWING: @P3768_A04_LIB.P3768_A04(SCH_1):PAGE12; MAX_WATTAGE: 62.5mW; NV_PN: 195-0004-000; PATH: I75; PHYS_PAGE: 12; PSPICETEMPLATE: X^@REFDES  %1    %2   @NV_PN; ROT: 2; SEC: 1; SIGNAL_MODEL: nv_res; TOL: 1 %; VER: 2; XY: (-5450,5200)
R184 = R: ASSEMBLY: BUTTON_MCU; CDS_LIB: discrete; CDS_PART_NAME: R_0402-10K,1 %,62.5MW,195-0004-000; CDS_PHYS_PART_NAME: R_0402-10K,1 %,62.5MW,195-0004-000-10K,195-0004-000; CDS_SEC: 1; DEVICE_TYPENAME: R_0402-10K1625MW195-0004-000-10K195-0004-000; DRAWING: @P3768_A04_LIB.P3768_A04(SCH_1):PAGE12; MAX_WATTAGE: 62.5mW; NV_PN: 195-0004-000; PATH: I76; PHYS_PAGE: 12; PSPICETEMPLATE: X^@REFDES  %1    %2   @NV_PN; ROT: 2; SEC: 1; SIGNAL_MODEL: nv_res; TOL: 1 %; VER: 2; XY: (-5200,5200)
R195 = R: ASSEMBLY: BUTTON_MCU; CDS_LIB: discrete; CDS_PART_NAME: R_0402-5.11K,1 %,62.5MW,195-0344-000; CDS_PHYS_PART_NAME: R_0402-5.11K,1 %,62.5MW,195-0344-000-195-0344-000,5.11K; CDS_SEC: 1; DEVICE_TYPENAME: R_0402-511K1625MW195-0344-000-195-0344-000511K; DRAWING: @P3768_A04_LIB.P3768_A04(SCH_1):PAGE12; MAX_WATTAGE: 62.5mW; NV_PN: 195-0344-000; PATH: I77; PHYS_PAGE: 12; PSPICETEMPLATE: X^@REFDES  %1    %2   @NV_PN; ROT: 2; SEC: 1; SIGNAL_MODEL: nv_res; TOL: 1 %; VER: 2; XY: (-2900,2400)
R196 = R#1: ASSEMBLY: BUTTON_MCU; CDS_LIB: discrete; CDS_PART_NAME: R_0402-100K,1 %,62.5MW,195-0005-000; CDS_PHYS_PART_NAME: R_0402-100K,1 %,62.5MW,195-0005-000-100K,195-0005-000; CDS_SEC: 1; CHIPS_PART_NAME: R; DEVICE_TYPENAME: R_0402-100K1625MW195-0005-000-100K195-0005-000; DRAWING: @P3768_A04_LIB.P3768_A04(SCH_1):PAGE12; MAX_WATTAGE: 62.5mW; NV_PN: 195-0005-000; PATH: I80; PHYS_PAGE: 12; PSPICETEMPLATE: X^@REFDES  %1    %2   @NV_PN; ROT: 2; SEC: 1; SIGNAL_MODEL: nv_res; TOL: 1 %; VER: 1; XY: (-1200,3300)
R197 = R: ASSEMBLY: BUTTON_MCU; CDS_LIB: discrete; CDS_PART_NAME: R_0402-100K,1 %,62.5MW,195-0005-000; CDS_PHYS_PART_NAME: R_0402-100K,1 %,62.5MW,195-0005-000-100K,195-0005-000; CDS_SEC: 1; DEVICE_TYPENAME: R_0402-100K1625MW195-0005-000-100K195-0005-000; DRAWING: @P3768_A04_LIB.P3768_A04(SCH_1):PAGE12; MAX_WATTAGE: 62.5mW; NV_PN: 195-0005-000; PATH: I87; PHYS_PAGE: 12; PSPICETEMPLATE: X^@REFDES  %1    %2   @NV_PN; ROT: 2; SEC: 1; SIGNAL_MODEL: nv_res; SKU: DNI; TOL: 1 %; VER: 2; XY: (-1100,2400)
R198 = R: ASSEMBLY: BUTTON_MCU; CDS_LIB: discrete; CDS_PART_NAME: R_0402-10K,1 %,62.5MW,195-0004-000; CDS_PHYS_PART_NAME: R_0402-10K,1 %,62.5MW,195-0004-000-10K,195-0004-000; CDS_SEC: 1; DEVICE_TYPENAME: R_0402-10K1625MW195-0004-000-10K195-0004-000; DRAWING: @P3768_A04_LIB.P3768_A04(SCH_1):PAGE12; MAX_WATTAGE: 62.5mW; NV_PN: 195-0004-000; PATH: I90; PHYS_PAGE: 12; PSPICETEMPLATE: X^@REFDES  %1    %2   @NV_PN; ROT: 2; SEC: 1; SIGNAL_MODEL: nv_res; SKU: DNI; TOL: 1 %; VER: 2; XY: (-4950,5200)
R203 = R: ASSEMBLY: BUTTON_MCU; CDS_LIB: discrete; CDS_PART_NAME: R_0402-100K,1 %,62.5MW,195-0005-000; CDS_PHYS_PART_NAME: R_0402-100K,1 %,62.5MW,195-0005-000-100K,195-0005-000; CDS_SEC: 1; DEVICE_TYPENAME: R_0402-100K1625MW195-0005-000-100K195-0005-000; DRAWING: @P3768_A04_LIB.P3768_A04(SCH_1):PAGE12; MAX_WATTAGE: 62.5mW; NV_PN: 195-0005-000; PATH: I94; PHYS_PAGE: 12; PSPICETEMPLATE: X^@REFDES  %1    %2   @NV_PN; ROT: 0; SEC: 1; SIGNAL_MODEL: nv_res; TOL: 1 %; VER: 2; XY: (-4400,2600)
R224 = R: ASSEMBLY: BUTTON_MCU; CDS_LIB: discrete; CDS_PART_NAME: R_0402-10K,1 %,62.5MW,195-0004-000; CDS_PHYS_PART_NAME: R_0402-10K,1 %,62.5MW,195-0004-000-10K,195-0004-000; CDS_SEC: 1; DEVICE_TYPENAME: R_0402-10K1625MW195-0004-000-10K195-0004-000; DRAWING: @P3768_A04_LIB.P3768_A04(SCH_1):PAGE12; MAX_WATTAGE: 62.5mW; NV_PN: 195-0004-000; PATH: I101; PHYS_PAGE: 12; PSPICETEMPLATE: X^@REFDES  %1    %2   @NV_PN; ROT: 2; SEC: 1; SIGNAL_MODEL: nv_res; TOL: 1 %; VER: 2; XY: (-4650,5200)
R225 = R#1: ASSEMBLY: BUTTON_MCU; CDS_LIB: discrete; CDS_PART_NAME: R_0402-0OHM,0.05 OHM,62.5MW,195-2655-000; CDS_PHYS_PART_NAME: R_0402-0OHM,0.05 OHM,62.5MW,195-2655-000-0OHM,195-2655-000; CDS_SEC: 1; CHIPS_PART_NAME: R; DEVICE_TYPENAME: R_0402-0OHM005OHM625MW195-2655-000-0OHM195-2655-000; DRAWING: @P3768_A04_LIB.P3768_A04(SCH_1):PAGE12; MAX_WATTAGE: 62.5mW; NV_PN: 195-2655-000; PATH: I102; PHYS_PAGE: 12; PSPICETEMPLATE: X^@REFDES  %1    %2   @NV_PN; ROT: 0; SEC: 1; SIGNAL_MODEL: nv_res; SKU: DNI; TOL: 0.05 ohm; VER: 1; XY: (-4450,3950)
R226 = R: ASSEMBLY: BUTTON_MCU; CDS_LIB: discrete; CDS_PART_NAME: R_0402-91K,5 %,62.5MW,195-0648-000; CDS_PHYS_PART_NAME: R_0402-91K,5 %,62.5MW,195-0648-000-195-0648-000,91K; CDS_SEC: 1; DEVICE_TYPENAME: R_0402-91K5625MW195-0648-000-195-0648-00091K; DRAWING: @P3768_A04_LIB.P3768_A04(SCH_1):PAGE12; MAX_WATTAGE: 62.5mW; NV_PN: 195-0648-000; PATH: I103; PHYS_PAGE: 12; PSPICETEMPLATE: X^@REFDES  %1    %2   @NV_PN; ROT: 0; SEC: 1; SIGNAL_MODEL: nv_res; TOL: 5 %; VER: 2; XY: (-1650,3100)
R227 = R#1: ASSEMBLY: BUTTON_MCU; CDS_LIB: discrete; CDS_PART_NAME: R_0402-10K,1 %,62.5MW,195-0004-000; CDS_PHYS_PART_NAME: R_0402-10K,1 %,62.5MW,195-0004-000-10K,195-0004-000; CDS_SEC: 1; CHIPS_PART_NAME: R; DEVICE_TYPENAME: R_0402-10K1625MW195-0004-000-10K195-0004-000; DRAWING: @P3768_A04_LIB.P3768_A04(SCH_1):PAGE12; MAX_WATTAGE: 62.5mW; NV_PN: 195-0004-000; PATH: I104; PHYS_PAGE: 12; PSPICETEMPLATE: X^@REFDES  %1    %2   @NV_PN; ROT: 2; SEC: 1; SIGNAL_MODEL: nv_res; SKU: DNI; TOL: 1 %; VER: 1; XY: (-5200,4350)
R228 = R#1: ASSEMBLY: BUTTON_MCU; CDS_LIB: discrete; CDS_PART_NAME: R_0402-10K,1 %,62.5MW,195-0004-000; CDS_PHYS_PART_NAME: R_0402-10K,1 %,62.5MW,195-0004-000-10K,195-0004-000; CDS_SEC: 1; CHIPS_PART_NAME: R; DEVICE_TYPENAME: R_0402-10K1625MW195-0004-000-10K195-0004-000; DRAWING: @P3768_A04_LIB.P3768_A04(SCH_1):PAGE12; MAX_WATTAGE: 62.5mW; NV_PN: 195-0004-000; PATH: I105; PHYS_PAGE: 12; PSPICETEMPLATE: X^@REFDES  %1    %2   @NV_PN; ROT: 2; SEC: 1; SIGNAL_MODEL: nv_res; SKU: DNI; TOL: 1 %; VER: 1; XY: (-5200,4150)
R525 = R: ASSEMBLY: BUTTON_MCU; CDS_LIB: discrete; CDS_PART_NAME: R_0402-1K,5 %,62.5MW,195-0485-000; CDS_PHYS_PART_NAME: R_0402-1K,5 %,62.5MW,195-0485-000-195-0485-000,1K; CDS_SEC: 1; DEVICE_TYPENAME: R_0402-1K5625MW195-0485-000-195-0485-0001K; DRAWING: @P3768_A04_LIB.P3768_A04(SCH_1):PAGE12; MAX_WATTAGE: 62.5mW; NV_PN: 195-0485-000; PATH: I114; PHYS_PAGE: 12; ROT: 2; SEC: 1; SIGNAL_MODEL: nv_res; TOL: 5 %; VER: 2; XY: (-7400,3550)
R542 = R#1: ASSEMBLY: BUTTON_MCU; CDS_LIB: discrete; CDS_PART_NAME: R_0402-1K,5 %,62.5MW,195-0485-000; CDS_PHYS_PART_NAME: R_0402-1K,5 %,62.5MW,195-0485-000-195-0485-000,1K; CDS_SEC: 1; CHIPS_PART_NAME: R; DEVICE_TYPENAME: R_0402-1K5625MW195-0485-000-195-0485-0001K; DRAWING: @P3768_A04_LIB.P3768_A04(SCH_1):PAGE12; MAX_WATTAGE: 62.5mW; NV_PN: 195-0485-000; PATH: I117; PHYS_PAGE: 12; ROT: 0; SEC: 1; SIGNAL_MODEL: nv_res; TOL: 5 %; VER: 1; XY: (-8400,4200)
TP9 = LABTESTPOINT#1: CDS_LIB: electro_mechanic; CDS_PART_NAME: LABTESTPOINT_PIN-LABTESTPOINT; CDS_PHYS_PART_NAME: LABTESTPOINT_PIN-LABTESTPOINT; CDS_SEC: 1; DEVICE_TYPENAME: LABTESTPOINT_PIN-LABTESTPOINT; DRAWING: @P3768_A04_LIB.P3768_A04(SCH_1):PAGE12; PACK_TYPE: PIN; PATH: I41; PHYS_PAGE: 12; ROT: 0; SEC: 1; VER: 1; XY: (-8750,3900)
TP10 = LABTESTPOINT#1: CDS_LIB: electro_mechanic; CDS_PART_NAME: LABTESTPOINT_PIN-LABTESTPOINT; CDS_PHYS_PART_NAME: LABTESTPOINT_PIN-LABTESTPOINT; CDS_SEC: 1; DEVICE_TYPENAME: LABTESTPOINT_PIN-LABTESTPOINT; DRAWING: @P3768_A04_LIB.P3768_A04(SCH_1):PAGE12; PACK_TYPE: PIN; PATH: I42; PHYS_PAGE: 12; ROT: 0; SEC: 1; VER: 1; XY: (-8750,3800)
TP11 = LABTESTPOINT#1: CDS_LIB: electro_mechanic; CDS_PART_NAME: LABTESTPOINT_PIN-LABTESTPOINT; CDS_PHYS_PART_NAME: LABTESTPOINT_PIN-LABTESTPOINT; CDS_SEC: 1; DEVICE_TYPENAME: LABTESTPOINT_PIN-LABTESTPOINT; DRAWING: @P3768_A04_LIB.P3768_A04(SCH_1):PAGE12; PACK_TYPE: PIN; PATH: I43; PHYS_PAGE: 12; ROT: 0; SEC: 1; VER: 1; XY: (-8750,3750)
TP12 = LABTESTPOINT: CDS_LIB: electro_mechanic; CDS_PART_NAME: LABTESTPOINT_PIN-LABTESTPOINT; CDS_PHYS_PART_NAME: LABTESTPOINT_PIN-LABTESTPOINT; CDS_SEC: 1; DEVICE_TYPENAME: LABTESTPOINT_PIN-LABTESTPOINT; DRAWING: @P3768_A04_LIB.P3768_A04(SCH_1):PAGE12; PACK_TYPE: PIN; PATH: I22; PHYS_PAGE: 12; ROT: 0; SEC: 1; VER: 3; XY: (-4850,4250)
U18 = U_CPU_EFM8SB1: ASSEMBLY: BUTTON_MCU; CDS_LIB: digital; CDS_PART_NAME: U_CPU_EFM8SB1_QFN20-EFM8SB10F2G-P3737,OTHER,190-13737-0000-000; CDS_PHYS_PART_NAME: U_CPU_EFM8SB1_QFN20-EFM8SB10F2G-P3737,OTHER,190-13737-0000-000-190-13737-0000-000; CDS_SEC: 1; DEVICE_TYPENAME: U_CPU_EFM8SB1_QFN20-EFM8SB10F2G-P3737OTHER190-13737-0000-000-190-13737-0000-000; DRAWING: @P3768_A04_LIB.P3768_A04(SCH_1):PAGE12; NV_NAME: EFM8SB10F2G-P3737; NV_PN: 190-13737-0000-000; PACK_TYPE: QFN20; PATH: I115; PHYS_PAGE: 12; ROT: 0; SEC: 1; TYPE: Other; VER: 1; XY: (-6350,4050)
U19 = U_BUF_OD: ASSEMBLY: BUTTON_MCU; CDS_LIB: logic; CDS_PART_NAME: U_BUF_OD_SC70_5-74LVC1G07GW/SN74LVC1G07DCKRE4,BUFFER - OPEN DRAIN,115-0138-000; CDS_PHYS_PART_NAME: U_BUF_OD_SC70_5-74LVC1G07GW/SN74LVC1G07DCKRE4,BUFFER - OPEN DRAIN,115-0138-000-115-0138-000; CDS_SEC: 1; DEVICE_TYPENAME: U_BUF_OD_SC70_5-74LVC1G07GWSN74LVC1G07DCKRE4BUFFER-OPENDRAIN115-0138-000-115-0138-000; DRAWING: @P3768_A04_LIB.P3768_A04(SCH_1):PAGE12; FUNCTION: Buffer - Open Drain; NV_NAME: 74LVC1G07GW/SN74LVC1G07DCKRE4; NV_PN: 115-0138-000; PATH: I54; PHYS_PAGE: 12; ROT: 2; SEC: 1; VER: 1; XY: (-3000,5750)
U22 = U_LEVSHFT_3STATE: ASSEMBLY: BUTTON_MCU; CDS_LIB: logic; CDS_PART_NAME: U_LEVSHFT_3STATE_SC70_5-SN74LV1T125,LEVEL SHIFTER,115-2747-000; CDS_PHYS_PART_NAME: U_LEVSHFT_3STATE_SC70_5-SN74LV1T125,LEVEL SHIFTER,115-2747-000-115-2747-000; CDS_SEC: 1; DEVICE_TYPENAME: U_LEVSHFT_3STATE_SC70_5-SN74LV1T125LEVELSHIFTER115-2747-000-115-2747-000; DRAWING: @P3768_A04_LIB.P3768_A04(SCH_1):PAGE12; FUNCTION: Level Shifter; NV_NAME: SN74LV1T125; NV_PN: 115-2747-000; PATH: I96; PHYS_PAGE: 12; ROT: 2; SEC: 1; VER: 10; XY: (-10250,4300)
U23 = U_LEVSHFT_3STATE: ASSEMBLY: BUTTON_MCU; CDS_LIB: logic; CDS_PART_NAME: U_LEVSHFT_3STATE_SC70_5-SN74LV1T125,LEVEL SHIFTER,115-2747-000; CDS_PHYS_PART_NAME: U_LEVSHFT_3STATE_SC70_5-SN74LV1T125,LEVEL SHIFTER,115-2747-000-115-2747-000; CDS_SEC: 1; DEVICE_TYPENAME: U_LEVSHFT_3STATE_SC70_5-SN74LV1T125LEVELSHIFTER115-2747-000-115-2747-000; DRAWING: @P3768_A04_LIB.P3768_A04(SCH_1):PAGE12; FUNCTION: Level Shifter; NV_NAME: SN74LV1T125; NV_PN: 115-2747-000; PATH: I97; PHYS_PAGE: 12; ROT: 2; SEC: 1; VER: 10; XY: (-4950,2750)

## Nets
3V3_AO: C34.1 C36.1 C135.1 R30.1 R139.1 R140.1 R141.1 R144.1 R183.1 R184.1 R198.1 R224.1 U6.5(OUT) U18.4(VDD) U19.5(VCC) U23.5(VCC) ; also on sheet 17 21
3V3_AO_ADJ: C34.2 R30.2 R31.1 U6.4(ADJ)
5V_PG_BUF_R: R165.2 U19.4(Y)
GND: C30.2 C31.2 C32.2 C36.2 C135.2 C142.2 C169.2 C408.2 C409.2 C410.2 C412.2 D66.2(A) Q29.2(S) Q60.2(S) Q61.2(S) R31.2 R137.2 R138.2 R166.2 R195.2 R197.2 R203.2 R227.1 R228.1 R516.2 R525.2 TP11.1 U5.2(GND1) U6.2(GND) U18.3(GND1) U18.12(GND2) U18.21(EPAD) U19.3(GND) U22.1(OE*) U22.3(GND) U23.1(OE*) U23.3(GND) ; also on sheet 1 2 3 4 5 6 7 8 9 10 11 12 15 16 17 18 19 21 25
VDD_1V8: C411.1 C412.1 R515.1 R563.1 U5.5(OUT) ; also on sheet 1 2 3 5 8 12 19 21
VDD_1V8_ADJ: C411.2 R515.2 R516.1 U5.4(GND2)
VDD_1V8_DISCHG: Q61.3(D) R563.2
VDD_3V3_SYS: C408.1 C409.1 C410.1 U5.1(IN) ; also on sheet 1 2 3 4 5 6 7 8 11 12 15 19 20 21
VDD_5V_SYS: C30.1 C31.1 C32.1 R562.1 U6.1(IN) U22.5(VCC) ; also on sheet 1 2 8 9 10 11 12 15 16 17 21
VDD_CVM: R170.1 ; also on sheet 17 21
VDD_DCIN: Q28.2(S) R196.1 ; also on sheet 18
VIN_PWR_ON: R542.1 ; also on sheet 17
VIN_PWR_ON_R: R525.1 R542.2 U18.10(P1_3)
BMCU_ACOK: C142.1 R144.2 R165.1 U18.16(P0_6) ; also on sheet 1
BMCU_BRD_SEL: R137.1 R139.2 U18.11(P1_2)
BMCU_C2CK: R140.2 TP10.1 U18.5(RST*)
BMCU_C2D: TP9.1 U18.6(P2_7_C2D)
BMCU_P01: R183.2 U18.1(P0)
BMCU_P02: R184.2 U18.20(P0_2)
BMCU_P03: R227.2 U18.19(P0_3)
BMCU_P05: R228.2 U18.17(P0_5)
BMCU_PGOOD: R224.2 R225.1 U18.15(P0_7)
BMCU_POWER_EN: R138.1 U18.9(P1_5) U22.2(IN)
BMCU_PWR_BTN*: D63.1(A1) D63.2(A2) R141.2 U18.2(P0_0)
BMCU_UART_TX: TP12.1 U18.18(P0_4)
BUCK_3V3_EN: U18.13(P1_1) U23.4(OUT) ; also on sheet 15
BUCK_3V3_PG: Q60.1(G) R225.2 U5.3(EN) ; also on sheet 8 11 15
BUCK_5V_PG: Q29.1(G) R197.1 U6.3(EN) U19.2(A) ; also on sheet 16
DCJ_UNPLUG: Q28.1(G) R196.2 R226.1
DCJ_UNPLUG_Q: Q28.3(D) R142.1
DCJ_UNPLUG_R: Q29.3(D) R226.2
DISCHG_1V8_SYS: Q60.3(D) Q61.1(G) R562.2
FORCE_OFF*: C169.1 D62.1(A1) D62.2(A2) D66.1(K) R142.2 R195.1 R198.2 U18.14(P1_0)
POWER_EN: R166.1 U22.4(OUT) ; also on sheet 21
PWR_BTN*: D63.3(CC) ; also on sheet 1 21
SHUTDOWN_REQ*: D62.3(CC) R170.2 ; also on sheet 21
SNN_BMCU_P17: U18.7(P1)
SNN_PWR_BTN_BUF*: U18.8(P1_6)
SYS_RST*: R203.1 U23.2(IN) ; also on sheet 1 21

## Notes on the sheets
sheet 13
- A
- B
- C
- D
- E
- F
- G
- H
- BUTTON MCU FOR POWER UP
- 1
- 1
- 2
- 2
- 3
- 3
- STATE DIAGRAM
- 4
- 4
- 5
- 5
- NVIDIA CORPORATION
- 2701 SAN TOMAS EXPRESSWAY
- SANTA CLARA, CA 95050, USA
- ASSEMBLY
- <ASSEMBLY_DESCRIPTION>
- PAGE DETAIL
- BUTTON MCU
- 600-13768-BASE-400
- NV_PN
- ALL NVIDIA DESIGN SPECIFICATIONS, REFERENCE SPECIFICATIONS, REFERENCE BOARDS, FILES, DRAWINGS, DIAGNOSTICS, LISTS AND OTHER DOCUMENTS OR INFORMATION (TOGETHER AND SEPARATELY, 'MATERIALS') ARE BEING PROVIDED 'AS IS'. THE MATERIALS MAY
- P3768-A04
- 12 OF 25
- CONTAIN KNOWN AND UNKNOWN VIOLATIONS OR DEVIATIONS OF INDUSTRY STANDARDS AND SPECIFICATIONS. NVIDIA MAKES NO WARRANTIES, EXPRESSED, IMPLIED, STATUTORY OR OTHERWISE WITH RESPECT TO THE MATERIALS OR OTHERWISE, AND EXPRESSLY DISCLAIMS ALL
- PCB REV
- PAGE
- IMPLIED WARRANTIES INCLUDING, WITHOUT LIMITATION, THE WARRANTIES OF DESIGN, OF NONINFRINGEMENT, MERCHANTABILITY OR FITNESS FOR A PARTICULAR PURPOSE, OR ARISING FROM A COURSE OF DEALING, TRADE USAGE, TRADE PRACTICE, OR INDUSTRY STANDARDS.
- BOM REV
- A
- DATE
- 27-FEB-2023
- A
- B
- C
- D
- E
- F
- G
- H
sheet 14
- A
- B
- C
- D
- E
- F
- G
- H
- 1V8 LDO AND 3V3 AO RAILS
- 1
- 1
- VDD_1V8 RAIL DISCHARGE
- 2
- 2
- VOUT=VREF(0.8V)* (1+(RT/RB))+Iadj(1nA)*Rt
- RT=124k
- RB=100k
- VOUT=1.792V
- 3
- 3
- Rt
- Rb
- VOUT=VREF(0.8V)* (1+(RT/RB))+Iadj(1nA)*Rt
- RT=309k
- 4
- 4
- RB=100k
- VOUT=3.272V
- 5
- 5
- NVIDIA CORPORATION
- 2701 SAN TOMAS EXPRESSWAY
- SANTA CLARA, CA 95050, USA
- ASSEMBLY
- <ASSEMBLY_DESCRIPTION>
- PAGE DETAIL
- 1V8 LDO & 3V3 AO Rails
- 600-13768-BASE-400
- NV_PN
- ALL NVIDIA DESIGN SPECIFICATIONS, REFERENCE SPECIFICATIONS, REFERENCE BOARDS, FILES, DRAWINGS, DIAGNOSTICS, LISTS AND OTHER DOCUMENTS OR INFORMATION (TOGETHER AND SEPARATELY, 'MATERIALS') ARE BEING PROVIDED 'AS IS'. THE MATERIALS MAY
- P3768-A04
- 11 OF 25
- CONTAIN KNOWN AND UNKNOWN VIOLATIONS OR DEVIATIONS OF INDUSTRY STANDARDS AND SPECIFICATIONS. NVIDIA MAKES NO WARRANTIES, EXPRESSED, IMPLIED, STATUTORY OR OTHERWISE WITH RESPECT TO THE MATERIALS OR OTHERWISE, AND EXPRESSLY DISCLAIMS ALL
- PCB REV
- PAGE
- IMPLIED WARRANTIES INCLUDING, WITHOUT LIMITATION, THE WARRANTIES OF DESIGN, OF NONINFRINGEMENT, MERCHANTABILITY OR FITNESS FOR A PARTICULAR PURPOSE, OR ARISING FROM A COURSE OF DEALING, TRADE USAGE, TRADE PRACTICE, OR INDUSTRY STANDARDS.
- BOM REV
- A
- DATE
- 27-FEB-2023
- A
- B
- C
- D
- E
- F
- G
- H
